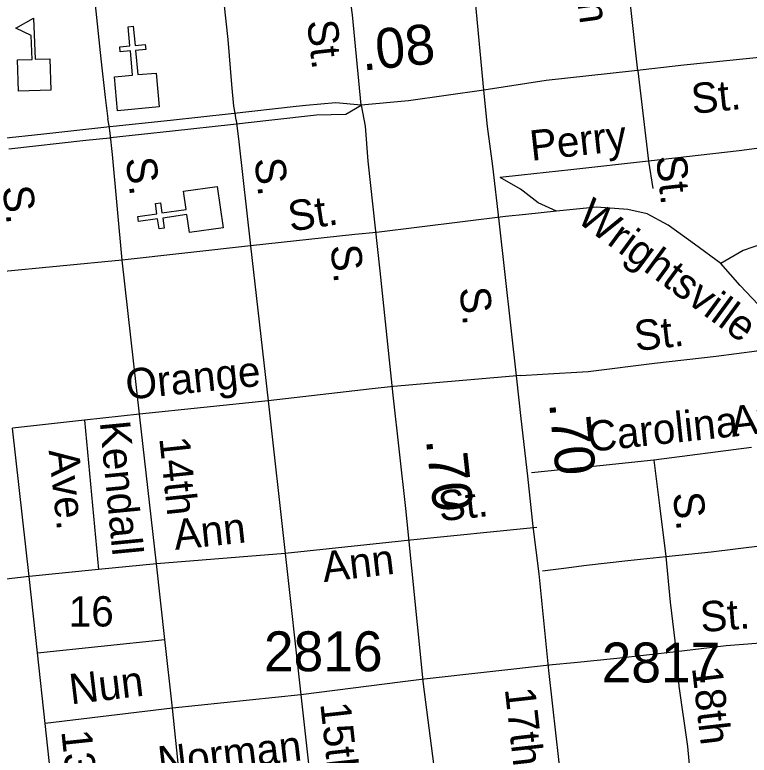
# Model space of a CAD drawing. Extents: x 2290055 to 2389491, y 66597 to 237875.
# Drawn here: x 2322658 to 2324958, y 176940 to 179258 of the extents above; entities that cross this region are included whole.
import ezdxf

# ---------------------------------------------------------------- set-up
doc = ezdxf.new("R2010")
doc.units = 0
for name, color, linetype in [('Exist Cultural Church CELL', 7, 'Continuous'), ('Exist Cultural Educational Facility High CELL', 7, 'Continuous'), ('Exist Road Non-System Type 51', 7, 'Continuous'), ('Exist Road Non-System Type 51 Label', 7, 'Continuous'), ('Exist Road Primary US Divided Attributed', 7, 'Continuous'), ('Exist Road Primary US Label', 7, 'Continuous'), ('Exist Road Primary US Mileage Hundredths English Label', 7, 'Continuous'), ('Exist Road Primary US UnDivided 4 Lane Attributed', 7, 'Continuous'), ('Exist Road Secondary Mileage Hundredths English Label', 7, 'Continuous'), ('Exist Road Secondary Type 51 Divided Attributed', 7, 'Continuous'), ('Exist Road Secondary Type 51 Label', 7, 'Continuous'), ('Exist Road Secondary Type 51 Number Label', 7, 'Continuous')]:
    doc.layers.add(name, color=color, linetype=linetype)

msp = doc.modelspace()

# ---------------------------------------------------------------- linework, layer by layer
at = {"layer": 'Exist Cultural Church CELL'}
for points in [[(2322970.4, 179064.3), (2323027.1, 179069.5), (2323020.2, 179145.4), (2322988.3, 179142.5), (2322986.9, 179158.4), (2323018.7, 179161.3), (2323013.3, 179221.2), (2323029.2, 179222.6), (2323034.7, 179162.7), (2323066.6, 179165.6), (2323068, 179149.7), (2323036.1, 179146.8), (2323043, 179071), (2323100.5, 179076.1), (2323110.1, 178970.1), (2322980, 178958.2)], [(2323204.8, 178576.4), (2323196.7, 178632.7), (2323121.3, 178621.9), (2323125.8, 178590.3), (2323110, 178588), (2323105.5, 178619.7), (2323045.9, 178611.2), (2323043.7, 178627.1), (2323103.2, 178635.6), (2323098.7, 178667.2), (2323114.5, 178669.5), (2323119, 178637.8), (2323194.4, 178648.6), (2323186.4, 178705.7), (2323291.7, 178720.7), (2323310.2, 178591.4)]]:
    msp.add_lwpolyline(points, close=True, dxfattribs=at)
at = {"layer": 'Exist Cultural Educational Facility High CELL'}
msp.add_lwpolyline([(2322669.4, 179019.3), (2322666, 179117.1), (2322712, 179118.8), (2322709.3, 179193.8), (2322661.4, 179216.4), (2322717, 179247.6), (2322721.6, 179119.1), (2322767.6, 179120.8), (2322771, 179022.9)], close=True, dxfattribs=at)
at = {"layer": 'Exist Road Non-System Type 51'}
for p, q in [((2323344.4, 178972.8), (2323338, 179040.2)), ((2322941.4, 179000), (2322949.9, 178932.8)), ((2323347.9, 178950.5), (2323344.4, 178972.8)), ((2323351.4, 178928.2), (2323347.9, 178950.5)), ((2322953.4, 178910.5), (2322949.9, 178932.8)), ((2323351.4, 178928.2), (2323359.6, 178861)), ((2322956.9, 178888.2), (2322953.4, 178910.5)), ((2322963.9, 178820.9), (2322956.9, 178888.2)), ((2322994.1, 178489.6), (2322963.9, 178820.9)), ((2324245.4, 178756), (2324178.2, 178748.5)), ((2324354.3, 178643.5), (2324258.2, 178633.6)), ((2324195.1, 178627), (2323790.8, 178577.2)), ((2324258.2, 178633.6), (2324195.1, 178627)), ((2323790.8, 178577.2), (2323723.5, 178570.1)), ((2323723.5, 178570.1), (2323396.3, 178535.4)), ((2323396.3, 178535.4), (2322994.1, 178489.6)), ((2323396.3, 178535.4), (2323451.7, 178049.5)), ((2322994.1, 178489.6), (2322599.5, 178452)), ((2323049, 178007.7), (2322994.1, 178489.6)), ((2324242.7, 178128.8), (2324310.3, 178132.8)), ((2324242.7, 178128.8), (2323844, 178094.9)), ((2323776.8, 178087.2), (2323451.7, 178049.5)), ((2323844, 178094.9), (2323776.8, 178087.2)), ((2323451.7, 178049.5), (2323049, 178007.7)), ((2323451.7, 178049.5), (2323504.4, 177571.5)), ((2323049, 178007.7), (2322876, 177988.6)), ((2323101.6, 177539.5), (2323049, 178007.7)), ((2322876, 177988.6), (2322650.7, 177963.7)), ((2322703.2, 177499.7), (2322650.7, 177963.7)), ((2324965.8, 177903.4), (2324659.2, 177863.3)), ((2324293.4, 177652.6), (2323896.9, 177612.9)), ((2323829.6, 177605.8), (2323504.4, 177571.5)), ((2323896.9, 177612.9), (2323829.6, 177605.8)), ((2323504.4, 177571.5), (2323101.6, 177539.5)), ((2323504.4, 177571.5), (2323554.1, 177129.4)), ((2323101.6, 177539.5), (2322920.5, 177521.4)), ((2323127.9, 177302.6), (2323101.6, 177539.5)), ((2322920.5, 177521.4), (2322703.2, 177499.7)), ((2324310.9, 177517.4), (2324378.1, 177525.8)), ((2322703.2, 177499.7), (2322312.8, 177454.4)), ((2322729.2, 177260.1), (2322703.2, 177499.7)), ((2323151.7, 177087.2), (2323127.9, 177302.6)), ((2322753.2, 177039.6), (2322729.2, 177260.1)), ((2324409.9, 177229.3), (2324342.6, 177222.6)), ((2324342.6, 177222.6), (2323940.4, 177178.5)), ((2323873.2, 177170), (2323554.1, 177129.4)), ((2323940.4, 177178.5), (2323873.2, 177170)), ((2323554.1, 177129.4), (2323151.7, 177087.2)), ((2323554.1, 177129.4), (2323607, 176655.3)), ((2323151.7, 177087.2), (2322753.2, 177039.6)), ((2323202.4, 176611.4), (2323151.7, 177087.2)), ((2322804.1, 176567.4), (2322753.2, 177039.6))]:
    msp.add_line(p, q, dxfattribs=at)
for points in [[(2324608.9, 179083.5), (2324587.3, 179280.9), (2324565, 179490.1)], [(2323338, 179040.2), (2323326.8, 179181.1), (2323307.8, 179354.3)], [(2322907.5, 179310.6), (2322927.1, 179121), (2322941.4, 179000)], [(2324608.9, 179083.5), (2324642.9, 178799.8)], [(2323359.6, 178861), (2323359.6, 178860.9), (2323396.3, 178535.4)], [(2325076.3, 178852), (2324927.1, 178832.3), (2324642.9, 178799.8)], [(2324642.9, 178799.8), (2324399.4, 178773.3), (2324245.4, 178756)], [(2324642.9, 178799.8), (2324656.5, 178714.6)], [(2324250.6, 178705.8), (2324241.6, 178712.9), (2324178.2, 178748.5)], [(2324354.3, 178643.5), (2324297.5, 178669.2), (2324250.6, 178705.8)], [(2324869.1, 178479.8), (2324786.7, 178540.5), (2324704.3, 178599.3), (2324638.9, 178634.8), (2324578.3, 178648.5), (2324479.8, 178656.4), (2324354.3, 178643.5)], [(2325105.7, 178563.3), (2325030.1, 178552.1), (2324939.4, 178520.6), (2324869.1, 178479.8)], [(2325084.3, 178242.2), (2325005, 178331.2), (2324929.7, 178410.3), (2324869.1, 178479.8)], [(2324310.3, 178132.8), (2324454.3, 178141.4), (2324661.3, 178167.3), (2324854.4, 178189.1), (2324981.7, 178206.3), (2325049.1, 178229), (2325084.3, 178242.2)], [(2322876, 177988.6), (2322920.5, 177521.4)], [(2324659.2, 177863.3), (2324489.9, 177846.5), (2324276.8, 177824.2)], [(2324659.2, 177863.3), (2324677, 177721.9), (2324697.4, 177562.6)], [(2324697.4, 177562.6), (2324838.6, 177576.4), (2324999.9, 177596.6)], [(2324378.1, 177525.8), (2324448.4, 177534.7), (2324577.8, 177550), (2324697.4, 177562.6)], [(2324697.4, 177562.6), (2324710.9, 177419), (2324729.2, 177263.9)], [(2322729.2, 177260.1), (2323127.9, 177302.6)], [(2325033.9, 177294), (2324886.4, 177281.9), (2324729.2, 177263.9)], [(2324729.2, 177263.9), (2324544, 177242.4), (2324409.9, 177229.3)], [(2324729.2, 177263.9), (2324737.4, 177156.2), (2324764.9, 176967.3), (2324781.9, 176787.8)]]:
    msp.add_lwpolyline(points, dxfattribs=at)
at = {"layer": 'Exist Road Primary US Divided Attributed'}
for points in [[(2323743.1, 178975.9), (2323663.3, 178983.3), (2323569.5, 178974.9), (2323539.4, 178971.7), (2323335.5, 178948.4), (2323145.7, 178927.2), (2322945.8, 178906.4), (2322748.5, 178884.4), (2322612.2, 178870)], [(2322638.9, 178839), (2322880.4, 178865.8), (2322955.9, 178873.7), (2322957.7, 178873.9), (2323151.9, 178895), (2323342.9, 178916.3), (2323463.4, 178929.5), (2323602.9, 178944.7), (2323695, 178947.8), (2323743.1, 178975.9)]]:
    msp.add_lwpolyline(points, dxfattribs=at)
at = {"layer": 'Exist Road Primary US UnDivided 4 Lane Attributed'}
for points in [[(2326945.4, 179380.2), (2326737.2, 179339.9), (2326643, 179322), (2326412.4, 179283.6), (2326215.5, 179258.1), (2326035.2, 179238.5), (2325921, 179228.2), (2325779.9, 179212.9), (2325468.4, 179177.1), (2325419, 179167.7), (2325176.4, 179145.6), (2325030.7, 179129.4), (2324753.2, 179101.2), (2324590, 179081.6), (2324321.9, 179052.6), (2324126.7, 179022.8)], [(2324126.7, 179022.8), (2323890.6, 178988.7), (2323743.1, 178975.9)]]:
    msp.add_lwpolyline(points, dxfattribs=at)
at = {"layer": 'Exist Road Secondary Type 51 Divided Attributed'}
for points in [[(2323743.1, 178975.9), (2323716.2, 179258.6), (2323697.4, 179394.6), (2323683.4, 179572.8), (2323655, 179784.2), (2323630.8, 179989.3), (2323604.5, 180198.3), (2324009.3, 180236.4)], [(2324126.7, 179022.8), (2324104.1, 179266.6), (2324089.2, 179437.9), (2324072.2, 179657.8), (2324055.3, 179829.9), (2324028.9, 180089.1), (2324009.3, 180236.4)], [(2324536.8, 175354), (2324499.6, 175684.8), (2324485.2, 175817.8), (2324456.2, 176064.1), (2324436.1, 176273.8), (2324409.7, 176502.3), (2324382.4, 176741.8), (2324353.9, 177000.1), (2324330.4, 177204.7), (2324300.6, 177508.1), (2324281.9, 177656.4), (2324264.4, 177813.3), (2324243.5, 177994), (2324230.7, 178118.4), (2324175.3, 178612.8), (2324155.7, 178784.1), (2324138.7, 178908.6), (2324126.7, 179022.8)], [(2323743.1, 178975.9), (2323755.8, 178909.8), (2323763.9, 178800), (2323801.5, 178456.8), (2323841.6, 178067.3), (2323882.1, 177712.7), (2323936.6, 177162), (2323969, 176913.1), (2323992, 176699.2), (2324019.8, 176481.6), (2324041.1, 176235.5), (2324065.8, 175991.7), (2324089.6, 175795.6), (2324109.3, 175618.3), (2324143.5, 175313.3)]]:
    msp.add_lwpolyline(points, dxfattribs=at)

# ---------------------------------------------------------------- texts
at = {"layer": 'Exist Road Non-System Type 51 Label'}
for s, rotation, p in [('18th', 277.7753, (2324395.8, 179472)), ('Perry', 6.2911, (2324276.2, 178801)), ('S.', 277.011, (2323005, 178808)), ('S.', 276.0363, (2323408.6, 178806.9)), ('St.', 276.2492, (2324666, 178814.5)), ('S.', 277.011, (2322618.9, 178718.9)), ('Wrightsville', 323.6363, (2324413.2, 178613.5)), ('St.', 8.6878, (2323521.4, 178579.4)), ('St.', 6.5491, (2324603.4, 178205.1)), ('Orange', 5.9358, (2323010, 178053.1)), ('Carolina', 6.1279, (2324457.1, 177889.4)), ('Ave.', 6.8159, (2324904.7, 177936.8)), ('Kendall', 275.4688, (2322924.1, 177983.2)), ('14th', 276.0194, (2323110.4, 177932.9)), ('Ave.', 276.1213, (2322763.9, 177894.1)), ('St.', 6.2805, (2323990, 177671.9)), ('S.', 276.1766, (2324718.9, 177759.9)), ('Ann', 6.0562, (2323160.5, 177582.7)), ('Ann', 6.7322, (2323626.2, 177481.8)), ('St.', 4.6783, (2324808.3, 177324.9)), ('18th', 276.6098, (2324778.7, 177213.9)), ('Nun', 6.8126, (2322834.1, 177098.8)), ('15th', 276.3493, (2323614.5, 177101.4)), ('13th', 276.0194, (2322803.6, 177015.1)), ('Norman', 6.5727, (2323111.6, 176872.3))]:
    msp.add_text(s, height=95, rotation=rotation, dxfattribs=at).set_placement(p)
msp.add_text('16', height=95, dxfattribs=at).set_placement((2322826.7, 177342.9))
at = {"layer": 'Exist Road Primary US Label'}
msp.add_text('St.', height=95, rotation=5.8884, dxfattribs=at).set_placement((2324781.3, 178947.7))
at = {"layer": 'Exist Road Primary US Mileage Hundredths English Label'}
msp.add_text('.08', height=125, rotation=5.8986, dxfattribs=at).set_placement((2323747.7, 179083.4))
at = {"layer": 'Exist Road Secondary Mileage Hundredths English Label'}
for rotation, p in [(275.5375, (2324331.3, 178042.6)), (276.2618, (2323945.4, 177927.8))]:
    msp.add_text('.70', height=125, rotation=rotation, dxfattribs=at).set_placement(p)
at = {"layer": 'Exist Road Secondary Type 51 Label'}
for s, rotation, p in [('St.', 276.354, (2323573.2, 179238.7)), ('S.', 275.993, (2323646.2, 178535.1)), ('S.', 275.6871, (2324050.6, 178402.7)), ('17th', 276.4257, (2324192.5, 177147.6))]:
    msp.add_text(s, height=95, rotation=rotation, dxfattribs=at).set_placement(p)
at = {"layer": 'Exist Road Secondary Type 51 Number Label'}
for s, p in [('2816', (2323438.2, 177202.7)), ('2817', (2324496, 177167.6))]:
    msp.add_text(s, height=125, dxfattribs=at).set_placement(p)

doc.saveas('drawing.dxf')
